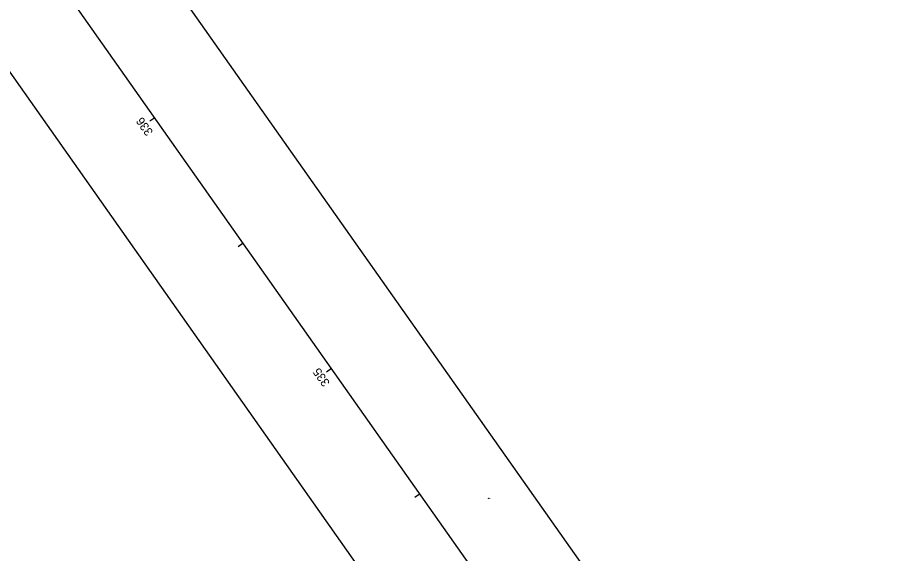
# Model space of a CAD drawing. Extents: x 1345023 to 1351589, y 535029 to 544731.
# Drawn here: x 1346354.3 to 1346641.1, y 543080.4 to 543255 of the extents above; entities that cross this region are included whole.
import ezdxf

# ---------------------------------------------------------------- set-up
doc = ezdxf.new("R2010")
doc.units = 0
for name, color, linetype in [('Default', 7, 'Continuous'), ('GE_X_CL_20', 7, 'Continuous'), ('RW_X_CL_20', 7, 'Continuous'), ('RW_X_Esmt_SH', 7, 'Continuous'), ('SV_P_Mon_Cells_Set', 7, 'Continuous'), ('SV_X_Text_Elevation', 7, 'Continuous'), ('SV_X_Text_Name', 7, 'Continuous')]:
    doc.layers.add(name, color=color, linetype=linetype)

msp = doc.modelspace()

# ---------------------------------------------------------------- linework, layer by layer
at = {"layer": 'Default'}
msp.add_circle((1346078.94, 543674.9), 1056.04, dxfattribs=at)
at = {"layer": 'GE_X_CL_20'}
for p, q in [((1346398.97, 543222.38), (1346397.34, 543221.23)), ((1346427.8, 543181.53), (1346426.17, 543180.37)), ((1346456.63, 543140.67), (1346454.99, 543139.52)), ((1346485.46, 543099.82), (1346483.82, 543098.67))]:
    msp.add_line(p, q, dxfattribs=at)
at = {"layer": 'RW_X_CL_20'}
msp.add_line((1348162.36, 540723.41), (1345880.07, 543957.73), dxfattribs=at)
msp.add_line((1348162.36, 540723.41), (1345880.07, 543957.73), dxfattribs=at)
at = {"layer": 'RW_X_Esmt_SH'}
for p, q in [((1348186.89, 540740.69), (1345904.58, 543975.03)), ((1348137.84, 540706.13), (1345855.56, 543940.44))]:
    msp.add_line(p, q, dxfattribs=at)
at = {"layer": 'SV_P_Mon_Cells_Set'}
for points in [[(1346507.92, 543098.36), (1346507.92, 543098.44)], [(1346507.92, 543098.44), (1346507.93, 543098.44)], [(1346507.92, 543098.36), (1346507.93, 543098.36)], [(1346507.97, 543098.37), (1346507.98, 543098.37), (1346507.98, 543098.37), (1346507.98, 543098.37), (1346507.98, 543098.36), (1346507.98, 543098.36), (1346507.98, 543098.36), (1346507.97, 543098.36), (1346507.97, 543098.36), (1346507.97, 543098.36), (1346507.97, 543098.37), (1346507.97, 543098.37), (1346507.97, 543098.37)], [(1346508, 543098.36), (1346508, 543098.44), (1346508.03, 543098.44), (1346508.03, 543098.44), (1346508.04, 543098.44), (1346508.04, 543098.44), (1346508.04, 543098.44), (1346508.04, 543098.43), (1346508.04, 543098.43), (1346508.04, 543098.43), (1346508.04, 543098.42), (1346508.04, 543098.42), (1346508.04, 543098.41), (1346508.04, 543098.41), (1346508.04, 543098.41), (1346508.04, 543098.4), (1346508.03, 543098.4), (1346508.03, 543098.4), (1346508, 543098.4)], [(1346508.09, 543098.37), (1346508.09, 543098.37), (1346508.09, 543098.37), (1346508.09, 543098.37), (1346508.09, 543098.36), (1346508.09, 543098.36), (1346508.09, 543098.36), (1346508.09, 543098.36), (1346508.08, 543098.36), (1346508.08, 543098.36), (1346508.08, 543098.37), (1346508.08, 543098.37), (1346508.09, 543098.37)], [(1346508.15, 543098.44), (1346508.15, 543098.44), (1346508.15, 543098.44), (1346508.15, 543098.44), (1346508.14, 543098.44), (1346508.14, 543098.44), (1346508.13, 543098.44), (1346508.13, 543098.44), (1346508.12, 543098.44), (1346508.12, 543098.43), (1346508.12, 543098.43), (1346508.12, 543098.42), (1346508.12, 543098.42), (1346508.12, 543098.41), (1346508.15, 543098.39), (1346508.15, 543098.39), (1346508.16, 543098.39), (1346508.16, 543098.38), (1346508.16, 543098.38), (1346508.16, 543098.38), (1346508.16, 543098.37), (1346508.15, 543098.37), (1346508.15, 543098.37), (1346508.15, 543098.37), (1346508.15, 543098.36), (1346508.15, 543098.36), (1346508.15, 543098.36), (1346508.14, 543098.36), (1346508.14, 543098.36), (1346508.13, 543098.36), (1346508.13, 543098.36), (1346508.12, 543098.37), (1346508.12, 543098.37)], [(1346508.19, 543098.37), (1346508.2, 543098.37), (1346508.2, 543098.37), (1346508.2, 543098.37), (1346508.2, 543098.36), (1346508.2, 543098.36), (1346508.2, 543098.36), (1346508.19, 543098.36), (1346508.19, 543098.36), (1346508.19, 543098.36), (1346508.19, 543098.37), (1346508.19, 543098.37), (1346508.19, 543098.37)]]:
    msp.add_lwpolyline(points, dxfattribs=at)
msp.add_circle((1346507.81, 543098.4), 0.06, dxfattribs=at)

# ---------------------------------------------------------------- texts
at = {"layer": 'GE_X_CL_20'}
for s, p in [('336', (1346398.57, 543217.75)), ('335', (1346456.22, 543136.05))]:
    msp.add_text(s, height=2.8, rotation=125.2086, dxfattribs=at).set_placement(p)
at = {"layer": 'SV_X_Text_Elevation'}
msp.add_text('857.15', height=0.06, dxfattribs=at).set_placement((1346507.56, 543098.34))
at = {"layer": 'SV_X_Text_Name'}
msp.add_text('SV1', height=0.06, dxfattribs=at).set_placement((1346507.7, 543098.4))

doc.saveas('drawing.dxf')
